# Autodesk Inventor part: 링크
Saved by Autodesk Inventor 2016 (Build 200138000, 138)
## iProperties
Created: 2024-08
Part Number: 링크
Material: 일반
Document SubType Name: Modeling
Designer: pc-2
Density: 1 g/cm^3
Appearance: 기본값
Author: jhkim
Sending System: Autodesk Inventor 2025
Preprocessor: ST-DEVELOPER v20
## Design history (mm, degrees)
node "링크1"
node "솔리드2"
node "솔리드1"
